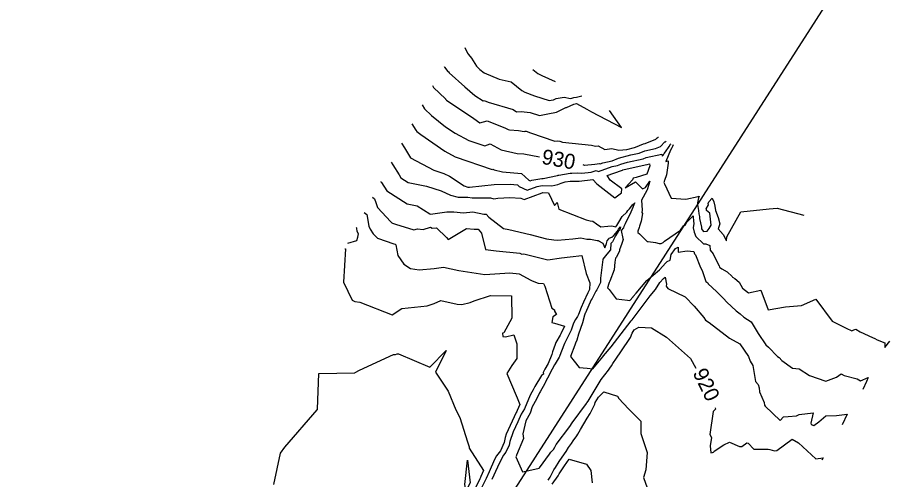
# Model space of a CAD drawing. Extents: x 1368651 to 1378602, y 762048 to 779328.
# Drawn here: x 1376956 to 1377539, y 763159 to 763468 of the extents above; entities that cross this region are included whole.
import ezdxf

# ---------------------------------------------------------------- set-up
doc = ezdxf.new("R2010")
doc.units = 0
for name, color, linetype in [('DTM Contours Major', 7, 'Continuous'), ('DTM Contours Major Text', 7, 'Continuous'), ('DTM Contours Minor', 7, 'Continuous'), ('Exist Plan Preparation Watershed Red', 7, 'Continuous')]:
    doc.layers.add(name, color=color, linetype=linetype)

msp = doc.modelspace()

# ---------------------------------------------------------------- linework, layer by layer
at = {"layer": 'DTM Contours Major'}
for points in [[(1377226.34, 763409.54), (1377228.05, 763406.79), (1377232.64, 763402.32), (1377242.04, 763394.83), (1377248.34, 763390.66), (1377257.44, 763385.77), (1377268.2, 763382.06), (1377271.73, 763383.39), (1377279.11, 763379.49), (1377289.89, 763377.04), (1377294.24, 763376.77), (1377304.68, 763374.81)], [(1377333.65, 763369.59), (1377334.52, 763369.28), (1377334.67, 763369.27), (1377334.74, 763369.27), (1377334.8, 763369.29), (1377341.71, 763369.89), (1377344.73, 763370.29), (1377345.25, 763370.09), (1377347.02, 763370.72), (1377353.34, 763372.05), (1377357.54, 763373.85), (1377365.81, 763376.03), (1377371.39, 763377.26), (1377375.08, 763378.85), (1377382.22, 763380.32), (1377385.45, 763381.63), (1377388.52, 763384.7), (1377388.76, 763384.81), (1377389.39, 763385.24)], [(1377193.17, 763347.84), (1377194.49, 763346.69), (1377195.46, 763344.29), (1377196.55, 763340.94), (1377205.54, 763331.33), (1377205.85, 763330.88), (1377206.12, 763330.62), (1377206.46, 763330.5), (1377208.63, 763329.75), (1377220.75, 763326.09), (1377223.31, 763326.66), (1377227.11, 763326.28), (1377231.97, 763327.88), (1377233.13, 763327.2), (1377236.03, 763327.31), (1377242.53, 763320.93), (1377243.83, 763319.6), (1377255.95, 763326.96), (1377261.15, 763326.53), (1377263.72, 763326.55), (1377266.01, 763323.75), (1377268.72, 763312.89), (1377275.71, 763311.98), (1377291.54, 763310.46), (1377292.92, 763309.72), (1377294.24, 763309.88), (1377310.24, 763306.02), (1377319.4, 763307.37), (1377325.11, 763307.88), (1377332.98, 763308.92), (1377335.89, 763296.77), (1377338.33, 763290.51), (1377338.2, 763286.11), (1377337.45, 763284.91), (1377336.97, 763284), (1377334.08, 763277.7), (1377332.51, 763274.22), (1377330.75, 763269.51), (1377330.18, 763268.24), (1377328.8, 763266.16), (1377327.46, 763263.75), (1377325.96, 763259.1), (1377324.58, 763256.27), (1377321.46, 763250), (1377320.92, 763249.05), (1377318.26, 763241.98), (1377318.09, 763241.49), (1377317.98, 763240.99), (1377315.28, 763236.56), (1377314.79, 763235.76), (1377311.65, 763229.97), (1377311.68, 763229.84), (1377308.56, 763223.96), (1377308.43, 763223.87), (1377308.2, 763223.49), (1377305.12, 763217.85), (1377304.78, 763217.13), (1377302.67, 763212.92), (1377299.92, 763207.87), (1377298.6, 763203.67), (1377295.57, 763198.44), (1377293.54, 763189.87), (1377293.96, 763186.55), (1377289.39, 763175.54), (1377289.33, 763175.39), (1377289.27, 763175.27), (1377288.93, 763174.43), (1377292.5, 763166.51), (1377293.32, 763164.36), (1377295.62, 763164.89), (1377304.45, 763166.79), (1377304.64, 763167.05), (1377304.68, 763167.09), (1377304.71, 763167.15), (1377311.43, 763176.28), (1377312.3, 763177.58), (1377313.99, 763179.21), (1377314.94, 763180.98), (1377315.9, 763182.65), (1377325, 763194.67), (1377326.6, 763197.22), (1377336.14, 763210.13), (1377336.45, 763210.55), (1377337.26, 763211.52), (1377345.96, 763225.99), (1377350.93, 763232.37), (1377351.71, 763233.65), (1377352.79, 763235.23), (1377353.72, 763236.65), (1377356.11, 763240.39), (1377359.12, 763244.55), (1377365.43, 763254.17), (1377366.66, 763256.98), (1377367.97, 763259.2), (1377371.18, 763260.92), (1377379.59, 763260.51), (1377389.57, 763254.28), (1377405.49, 763240.06), (1377409.07, 763233.67)], [(1377422.1, 763207.07), (1377422.31, 763206.34), (1377420.62, 763204.69), (1377418.51, 763189.42), (1377419.71, 763187.29), (1377418.76, 763181.85), (1377419.16, 763177.08), (1377420.35, 763177.41), (1377420.98, 763177.51), (1377421.22, 763177.77), (1377421.45, 763178.1), (1377427.92, 763182.39), (1377431.72, 763184.1), (1377438.38, 763181.27), (1377439.94, 763181.41), (1377443.27, 763183.82), (1377444.18, 763183.46), (1377447.88, 763179.56), (1377457.43, 763179.52), (1377458.55, 763179.33), (1377461.72, 763178.5), (1377463.19, 763178.75), (1377473.46, 763186.11), (1377477.73, 763183.82), (1377489.27, 763173.11), (1377494.08, 763173.75), (1377493.32, 763172.09)]]:
    msp.add_lwpolyline(points, dxfattribs=at)
at = {"layer": 'DTM Contours Minor'}
for points in [[(1377254.92, 763447.86), (1377256.59, 763443.93), (1377257.28, 763443.07), (1377259.31, 763440.73), (1377262.59, 763435.26), (1377265, 763433.13), (1377267.84, 763430.76), (1377277.72, 763426.73), (1377285.84, 763424.93), (1377292.98, 763419.05), (1377294.92, 763418.02), (1377301.3, 763415.44), (1377311.18, 763412.31), (1377312.63, 763412.62), (1377314.15, 763412.89), (1377315.77, 763413.71), (1377321.22, 763414.64), (1377325.44, 763413.61), (1377326.39, 763414.03), (1377327.77, 763414.39), (1377329.51, 763414.7), (1377332.99, 763415.56)], [(1377241.18, 763435.15), (1377241.4, 763434.63), (1377243.63, 763431.85), (1377243.9, 763431.54), (1377244.34, 763430.8), (1377254.9, 763421.46), (1377261.65, 763415.82), (1377267.02, 763412.08), (1377267.84, 763412.31), (1377270.49, 763411.24), (1377287.15, 763406.37), (1377289.44, 763404.78), (1377292.4, 763405.14), (1377298.58, 763404.34), (1377304.73, 763402.4), (1377310.25, 763403.58), (1377316.07, 763404.62), (1377322.26, 763407.75), (1377322.52, 763407.79), (1377322.72, 763407.74), (1377327.68, 763409.96), (1377329.52, 763410.43), (1377336.36, 763406.58), (1377339.49, 763404.78), (1377359.42, 763394.24), (1377351.44, 763405.64)], [(1377300.3, 763433.13), (1377303.56, 763430.44), (1377306.34, 763428.97), (1377315.19, 763425.12)], [(1377233.23, 763422.35), (1377234.01, 763421.1), (1377241.89, 763413.42), (1377242.01, 763413.27), (1377242.63, 763412.71), (1377260.95, 763400.27), (1377264.88, 763397.54), (1377269.84, 763398.89), (1377281.57, 763394.14), (1377283.75, 763392.99), (1377284.7, 763392.78), (1377290.63, 763392.41), (1377294.45, 763391.72), (1377295.14, 763391.86), (1377295.89, 763391.81), (1377298.73, 763390.79), (1377314.96, 763385.26), (1377317.08, 763385.51), (1377318.33, 763385.2), (1377320.19, 763384.53), (1377339.5, 763382.59), (1377342.11, 763381.83), (1377343.98, 763382.08), (1377348.3, 763379.76), (1377353.08, 763380.4), (1377357.77, 763379.28), (1377363.05, 763379.61), (1377368.1, 763380.94), (1377368.9, 763381.12), (1377374.29, 763383.43), (1377375.22, 763383.62), (1377382.37, 763386.52), (1377383.37, 763387.51), (1377384.08, 763387.83), (1377384.3, 763387.98)], [(1377219.45, 763396.72), (1377222.1, 763392.49), (1377222.82, 763391.78), (1377225.44, 763389.69), (1377241.59, 763378.49), (1377248.43, 763374.82), (1377273.14, 763366.31), (1377273.57, 763366.47), (1377274.48, 763366), (1377280.07, 763364.72), (1377292.72, 763363.72), (1377297.69, 763359.11), (1377298.59, 763358.7), (1377299.69, 763359.12), (1377306.22, 763360.33), (1377307.29, 763360.31), (1377316.77, 763362.25), (1377317.17, 763362.41), (1377317.66, 763362.55), (1377325.13, 763363.93), (1377326.39, 763363.91), (1377330.11, 763364.12), (1377332.99, 763363.89), (1377339.29, 763364.62), (1377342.65, 763365.59), (1377344.2, 763365), (1377353.29, 763368.23), (1377356.73, 763368.95), (1377359.01, 763369.93), (1377363.52, 763371.12), (1377373.88, 763373.41), (1377375.87, 763374.27), (1377386.51, 763376.47), (1377386.69, 763375.1), (1377387.5, 763376.17), (1377388.06, 763376.98), (1377388.78, 763378.09), (1377391.29, 763381.58), (1377392.31, 763383.16), (1377392.64, 763383.49)], [(1377212.56, 763383.91), (1377214.59, 763380.66), (1377218.66, 763374.19), (1377234.17, 763365.8), (1377240.77, 763363.72), (1377244.57, 763361.95), (1377254.5, 763355.4), (1377256.89, 763354.6), (1377257.96, 763354.43), (1377274.49, 763356.19), (1377285.15, 763356.4), (1377290.08, 763356.01), (1377291.26, 763354.92), (1377296.56, 763352.45), (1377303.11, 763354.95), (1377306.59, 763355.59), (1377312.94, 763355.48), (1377317.03, 763356.32), (1377319.22, 763357.18), (1377321.95, 763357.97), (1377325.26, 763358.58), (1377329.36, 763358.51), (1377330.46, 763358.57), (1377331.31, 763358.51), (1377340.4, 763359.56), (1377343, 763356.72), (1377354.99, 763347.32), (1377359.41, 763350.72), (1377359.76, 763353.32), (1377351.97, 763359.25), (1377350.03, 763362.35), (1377359.55, 763365.73), (1377360.12, 763365.85), (1377360.49, 763366.01), (1377361.23, 763366.2), (1377376.37, 763369.56), (1377376.66, 763369.69), (1377378.24, 763370.02), (1377378.4, 763368.83), (1377376.37, 763363.1), (1377369.4, 763361.02), (1377367.25, 763360.43), (1377366.79, 763359.4), (1377361.88, 763354.15), (1377368.8, 763358.08), (1377373.51, 763353.3), (1377375.48, 763354.37), (1377378.52, 763358.59), (1377376.65, 763352.79), (1377376.65, 763352.71), (1377376.38, 763352.27), (1377372.92, 763345.71), (1377373.28, 763339.19), (1377373.17, 763337.5), (1377373.46, 763337.02), (1377372.6, 763331.8), (1377371.58, 763328.5), (1377371.32, 763327.65), (1377370.39, 763325.04), (1377370.46, 763324.22), (1377371.59, 763323.39), (1377376.7, 763318.2), (1377377.41, 763318.13), (1377382.25, 763317.61), (1377384.7, 763316.82), (1377385.92, 763316.82), (1377387.26, 763317.46), (1377388.26, 763318.47), (1377398.98, 763325.85), (1377400.93, 763328.66), (1377401.99, 763329.11), (1377402.39, 763329.87), (1377402.88, 763330.82), (1377403.84, 763331.79), (1377406.38, 763334.46), (1377407.3, 763335.25), (1377407.38, 763334.88), (1377407.48, 763331.74), (1377407.82, 763330.28), (1377407.41, 763327.33), (1377407.92, 763324.51), (1377409.18, 763321.49), (1377414.28, 763316.57), (1377415.72, 763316.69), (1377418.41, 763315.54), (1377418.73, 763312.44), (1377420.8, 763309.98), (1377421.27, 763308.81), (1377424.69, 763301.98), (1377424.99, 763301.06), (1377426.52, 763299.99), (1377430.05, 763298.07), (1377433.4, 763294.91), (1377433.6, 763294.49), (1377435.14, 763293.56), (1377438.18, 763290.99), (1377440.34, 763287.11), (1377444.35, 763284.03), (1377452.58, 763285.8), (1377457.41, 763272.57), (1377468.92, 763274.61), (1377479.64, 763275.47), (1377489.27, 763279.73), (1377500.12, 763265.06), (1377509.58, 763260.38), (1377513.32, 763258.61), (1377514.7, 763259.25), (1377516.02, 763259.63), (1377518.93, 763257.87), (1377527.06, 763254.17), (1377528.69, 763253.52), (1377530.19, 763252.61), (1377535.38, 763250.45), (1377535.28, 763247.48), (1377538.79, 763251.57)], [(1377394.05, 763382.74), (1377393.47, 763381.55), (1377393.27, 763381.18), (1377393.08, 763380.81), (1377392.13, 763379.13), (1377389.05, 763371.69), (1377390.63, 763371.98), (1377390.65, 763370.62), (1377389.49, 763362.74), (1377388.32, 763359.05), (1377388.1, 763358.44), (1377387.92, 763358.06), (1377387.84, 763357.51), (1377388.16, 763356.82), (1377392.57, 763347.11), (1377402.36, 763346.59), (1377402.36, 763346.59), (1377410.64, 763348.38), (1377411.28, 763348.47), (1377411.07, 763347.72), (1377410.99, 763347.47), (1377410.15, 763344.12), (1377410.28, 763342.92), (1377410.42, 763341.68), (1377410.98, 763339.02), (1377411.2, 763336.74), (1377411.6, 763334.84), (1377411.64, 763333.66), (1377412.97, 763327.9), (1377412.88, 763327.27), (1377412.99, 763326.66), (1377413.26, 763326.01), (1377414.36, 763324.95), (1377416.72, 763325.15), (1377417.98, 763326.79), (1377419.3, 763329.18), (1377418.42, 763337.17), (1377416.32, 763338.99), (1377416.2, 763339.57), (1377416.06, 763340.08), (1377417.49, 763342.7), (1377417.38, 763343.61), (1377417.74, 763344.77), (1377419.94, 763347.15), (1377421.11, 763344.69), (1377421.8, 763341.74), (1377422.22, 763338.81), (1377423.99, 763334.18), (1377425.15, 763330.03), (1377423.97, 763326.66), (1377427.32, 763322.85), (1377428.25, 763321.27), (1377429.34, 763318.9), (1377429.51, 763318.7), (1377429.61, 763318.89), (1377429.77, 763321.27), (1377439.27, 763337.96), (1377458.14, 763340.06), (1377463.54, 763340.55), (1377481.37, 763335.8)], [(1377205.67, 763371.09), (1377206.73, 763369.39), (1377210.92, 763362.75), (1377212.2, 763360.82), (1377217.06, 763357.7), (1377229.19, 763355.12), (1377239.13, 763351.99), (1377245.26, 763349.12), (1377250.46, 763347.85), (1377256.99, 763347.89), (1377259.78, 763347.48), (1377272.06, 763347.43), (1377274.18, 763346.78), (1377276.91, 763347.25), (1377284.93, 763347.68), (1377292.35, 763347.21), (1377294.54, 763346.2), (1377306.53, 763350.77), (1377306.96, 763350.85), (1377310.75, 763350.79), (1377314.83, 763342.31), (1377316.58, 763344.32), (1377317.76, 763339.78), (1377335.87, 763332.67), (1377338.64, 763332.06), (1377340.32, 763331.89), (1377342.87, 763329.91), (1377345.63, 763328), (1377350.28, 763328.51), (1377352.97, 763328.77), (1377355.64, 763328.02), (1377355.64, 763328.01), (1377355.64, 763328.02), (1377356.36, 763328.94), (1377356.36, 763328.94), (1377357.8, 763331.02), (1377357.81, 763331.03), (1377360.03, 763334.95), (1377360.04, 763334.95), (1377363.16, 763337.88), (1377363.68, 763338.83), (1377364.75, 763340.05), (1377366.42, 763342.06), (1377366.94, 763342.68), (1377368.43, 763344.13), (1377367.79, 763342.62), (1377367.04, 763340.89), (1377365.77, 763337.75), (1377364.85, 763335.81), (1377363.65, 763333.76), (1377361.86, 763330.11), (1377361.17, 763328.31), (1377360.94, 763327.39), (1377359.31, 763325.59), (1377360.31, 763320.14), (1377360.63, 763319.51), (1377360.43, 763318.89), (1377359.77, 763316.91), (1377358.19, 763312.63), (1377358.24, 763311.98), (1377356.07, 763307.73), (1377355.51, 763307.07), (1377355.09, 763304.52), (1377354.53, 763299.26), (1377351.75, 763291.8), (1377351.32, 763290.85), (1377350.99, 763290.23), (1377350.07, 763287.29), (1377351.17, 763286.14), (1377355.92, 763279.85), (1377363.6, 763279.05), (1377365.15, 763278.8), (1377367.32, 763281.32), (1377367.37, 763281.38), (1377369.24, 763283.63), (1377376.46, 763292.14), (1377384.83, 763299.21), (1377389.13, 763304.07), (1377390, 763304.78), (1377392, 763305.74), (1377392.77, 763309.62), (1377395.48, 763313.53), (1377397.42, 763314.36), (1377397.25, 763313.05), (1377397.44, 763311.06), (1377403.3, 763311.93), (1377407.82, 763311.6), (1377408.33, 763309.98), (1377408.95, 763309.26), (1377412.34, 763300.9), (1377413.35, 763298.9), (1377415.71, 763291.53), (1377417.08, 763290.57), (1377417.43, 763289.89), (1377422.93, 763284.77), (1377427.69, 763280.26), (1377429.87, 763277.78), (1377436.03, 763271.93), (1377438.82, 763270), (1377441.19, 763267.7), (1377446.12, 763264.51), (1377450.87, 763256.87), (1377455.91, 763249.29), (1377457.61, 763247.66), (1377463.59, 763241.38), (1377464.77, 763240.76), (1377466.59, 763238.74), (1377473.65, 763233.64), (1377478.26, 763233.27), (1377485.07, 763228.71), (1377495.94, 763225.05), (1377503.12, 763227.66), (1377506.1, 763229.85), (1377508.28, 763228.67), (1377516.96, 763226.57), (1377519.15, 763225.08), (1377524.23, 763227.29), (1377523.06, 763224.77), (1377520.61, 763219.35)], [(1377198.78, 763358.27), (1377198.87, 763358.13), (1377199.24, 763357.55), (1377202.82, 763352.14), (1377216.47, 763343.39), (1377223.06, 763341.99), (1377231.46, 763336.59), (1377231.84, 763336.47), (1377231.92, 763336.42), (1377232, 763336.42), (1377242.87, 763337.96), (1377244.53, 763337.93), (1377247.44, 763338.06), (1377253.99, 763337.31), (1377260.21, 763338.03), (1377267.67, 763336.53), (1377269.2, 763336.54), (1377270.91, 763334.46), (1377280.69, 763326.94), (1377284.26, 763326.12), (1377298.41, 763322.99), (1377309.45, 763319.99), (1377314.3, 763319.25), (1377316.87, 763319.05), (1377327.06, 763319.96), (1377332.43, 763320.67), (1377336.3, 763319.82), (1377338.71, 763319.75), (1377343.28, 763318.91), (1377343.49, 763318.84), (1377343.92, 763318.9), (1377344.22, 763318.82), (1377344.19, 763318.63), (1377347.03, 763317.09), (1377348.43, 763314.01), (1377349.29, 763316.17), (1377349.57, 763316.92), (1377349.57, 763316.97), (1377349.88, 763318.66), (1377351.06, 763319.98), (1377351.26, 763320.53), (1377352.99, 763321.02), (1377353.16, 763321.2), (1377353.49, 763321.53), (1377354.4, 763322.18), (1377356.87, 763325.12), (1377357.36, 763326.24), (1377357.51, 763326.43), (1377358.92, 763327.92), (1377358.46, 763326.11), (1377357.28, 763324.8), (1377355.49, 763322.06), (1377353.45, 763317.94), (1377353.25, 763317.71), (1377353.15, 763317.6), (1377352.91, 763317.24), (1377352.31, 763316.79), (1377352.05, 763312.74), (1377352.07, 763312.46), (1377352.04, 763312.41), (1377348.83, 763308.58), (1377347.02, 763306.45), (1377346.95, 763306.48), (1377346.98, 763306.28), (1377345.46, 763293.68), (1377345.47, 763290.82), (1377342.92, 763285.89), (1377342.38, 763285.02), (1377339.81, 763280.22), (1377339.33, 763279.16), (1377335.45, 763270.59), (1377335.33, 763270.26), (1377334.74, 763269.05), (1377333.42, 763263.88), (1377330.73, 763256.37), (1377329.64, 763252.22), (1377328.83, 763250.3), (1377328.41, 763249.06), (1377325.37, 763241.39), (1377327.8, 763238.32), (1377331.21, 763234.16), (1377336.56, 763233.7), (1377340.39, 763233.23), (1377347, 763241.2), (1377347.55, 763241.84), (1377352.49, 763247.79), (1377366.04, 763265.18), (1377366.72, 763265.96), (1377367.24, 763266.69), (1377367.39, 763266.86), (1377378.55, 763281.89), (1377382.25, 763286.17), (1377385.1, 763290.73), (1377387.56, 763293.5), (1377388.71, 763294.45), (1377389.51, 763289.78), (1377389.28, 763288.28), (1377390.39, 763286.73), (1377401.91, 763281.33), (1377408.11, 763275), (1377414.4, 763267.54), (1377415.54, 763265.77), (1377418.15, 763264.08), (1377431.59, 763253.74), (1377438.53, 763249.78), (1377444.21, 763241.36), (1377445.47, 763238.29), (1377447.26, 763235.31), (1377449.01, 763224.63), (1377450.87, 763222.74), (1377451.49, 763220.4), (1377451.73, 763217.72), (1377454.8, 763210.77), (1377455.01, 763208.99), (1377455.39, 763208.28), (1377465.49, 763198.58), (1377467.74, 763201.11), (1377470.81, 763201.36), (1377476.3, 763201.85), (1377478.06, 763202.7), (1377487.61, 763203.81), (1377485.87, 763196.97), (1377486.11, 763196.11), (1377487.93, 763195.31), (1377491.18, 763197.81), (1377495.94, 763201.76), (1377502.98, 763202.02), (1377510.26, 763202.99), (1377506.97, 763195.72)], [(1377187.69, 763337.65), (1377189.32, 763336.23), (1377190.72, 763328.42), (1377191.72, 763326.45), (1377193.66, 763323.31), (1377196.6, 763320.48), (1377207.36, 763316.74), (1377208.43, 763316.37), (1377208.89, 763315.89), (1377210.16, 763308.8), (1377214.11, 763303.04), (1377218.7, 763300.2), (1377224.39, 763299.36), (1377234.34, 763300.09), (1377240.71, 763301.04), (1377250.91, 763298.79), (1377268.14, 763296.27), (1377284.82, 763297.24), (1377291.19, 763296.63), (1377299.03, 763292.38), (1377299.77, 763291.93), (1377303.9, 763290.39), (1377307.42, 763290.18), (1377308.33, 763288.42), (1377313.01, 763273.79), (1377314.82, 763272.66), (1377314.73, 763271.6), (1377316.05, 763269.55), (1377313.57, 763267.96), (1377312.99, 763264.05), (1377314.83, 763263.76), (1377321.39, 763261.62), (1377318.91, 763256.55), (1377318.44, 763255.61), (1377315.71, 763250.8), (1377315.22, 763249.5), (1377313.45, 763244.61), (1377313.06, 763242.82), (1377310.63, 763236.77), (1377308.29, 763232.94), (1377307.16, 763230.84), (1377307.38, 763229.65), (1377306, 763228.64), (1377301.62, 763221.4), (1377300.41, 763219.19), (1377299.55, 763217.63), (1377298.49, 763215.7), (1377294.62, 763206.42), (1377292.57, 763202.88), (1377290.17, 763197.77), (1377287.1, 763191.16), (1377285, 763184.67), (1377284.51, 763182.2), (1377282.22, 763177.55), (1377280.67, 763175.52), (1377277.57, 763169.56), (1377276.68, 763167.53), (1377272.89, 763159.18)], [(1377176.64, 763317.08), (1377182.69, 763318.8), (1377183.37, 763321.18), (1377183.85, 763323.31), (1377183.07, 763324.85), (1377182.68, 763327.06), (1377182.22, 763327.46)], [(1377174.66, 763313.32), (1377175.29, 763313.33), (1377173.94, 763290.97), (1377179.58, 763279.1), (1377181.43, 763278.08), (1377184.68, 763277.7), (1377206.43, 763269.32), (1377212.83, 763273.54), (1377229.82, 763275.33), (1377234.39, 763276.8), (1377238.76, 763278.79), (1377249.86, 763276.37), (1377252.93, 763276.11), (1377258.42, 763277.48), (1377261.13, 763278.51), (1377272.01, 763282.13), (1377285.98, 763281.92), (1377286.36, 763267.12), (1377281.02, 763257.15), (1377280.03, 763257.04), (1377280.22, 763254.83), (1377282.05, 763254.51), (1377287.67, 763255.82), (1377289.61, 763249.9), (1377289.7, 763240.08), (1377286.37, 763235.44), (1377282.83, 763230.05), (1377289.14, 763215.32), (1377289.25, 763215.03), (1377289.27, 763215.02), (1377291.53, 763209.34), (1377289.86, 763205.33), (1377289.55, 763204.8), (1377289.19, 763204.03), (1377282.47, 763189.59), (1377281.73, 763187.31), (1377281.08, 763184.04), (1377278.59, 763178.39), (1377276.07, 763175.09), (1377274.77, 763172.6), (1377271.16, 763164.37), (1377269.14, 763159.93), (1377265.06, 763151.84)], [(1377127.43, 763155.99), (1377131.75, 763176.95), (1377134.69, 763180.87), (1377156.32, 763205.84), (1377156.4, 763205.95), (1377156.4, 763205.97), (1377156.43, 763206.31), (1377157.31, 763230.07), (1377181.43, 763230.6), (1377181.54, 763230.78), (1377181.54, 763230.78), (1377184.48, 763232.2), (1377207.34, 763242.77), (1377208.55, 763242.72), (1377209.72, 763243.21), (1377210.64, 763243.31), (1377231.43, 763234.32), (1377242.44, 763245.39), (1377235.18, 763230.93), (1377243.84, 763218.27), (1377248.95, 763205.85), (1377251.49, 763200.78), (1377256.67, 763184.39), (1377257.75, 763181.06), (1377257.85, 763180.27), (1377267.42, 763165.28), (1377265.63, 763161.21), (1377265.39, 763160.68), (1377264.91, 763159.72), (1377259.16, 763147.61)], [(1377310.47, 763158.94), (1377311.92, 763160.9), (1377314.37, 763165.77), (1377315.49, 763167.38), (1377317.94, 763171.21), (1377319.97, 763174.13), (1377322.57, 763177.89), (1377324.07, 763180.72), (1377326.22, 763183.26), (1377327.2, 763185.08), (1377329.7, 763188.43), (1377330.36, 763189.6), (1377332.06, 763192.74), (1377336.53, 763200.3), (1377338.49, 763203.27), (1377341.67, 763209.51), (1377342.02, 763210.76), (1377344.17, 763214.37), (1377347.65, 763217.87), (1377356.72, 763214.85), (1377357.72, 763213.33), (1377364.27, 763206.48), (1377372.45, 763198.24), (1377372.45, 763190.06), (1377376.57, 763177.38), (1377375.75, 763165.66), (1377374.11, 763160.57), (1377376.61, 763153.76)], [(1377313.11, 763156.24), (1377317.23, 763161.83), (1377317.9, 763163.17), (1377321.06, 763167.69), (1377321.51, 763168.38), (1377324.56, 763172.79), (1377336.16, 763169.55), (1377339, 763165.35), (1377340.02, 763157.09)], [(1377254.85, 763155.92), (1377256.61, 763172.28), (1377258.49, 763157.09), (1377256.95, 763154.16), (1377255.64, 763152.13), (1377254.85, 763155.92)]]:
    msp.add_lwpolyline(points, dxfattribs=at)
at = {"layer": 'Exist Plan Preparation Watershed Red'}
msp.add_lwpolyline([(1373597.06, 767081.43), (1372938.47, 765818.8), (1372653.04, 765271.58), (1372900.45, 763223.22), (1372954.35, 762776.96), (1374508.77, 762195.85), (1375573.49, 762047.77), (1376441.31, 762392.26), (1376924.99, 762584.25), (1377201.49, 763017.52), (1377601.94, 763641.51), (1377736.1, 764021.28), (1377789.42, 764495.73), (1377827.52, 764834.78), (1378601.52, 765333.49), (1378471.1, 765535.9), (1378572.78, 766627.53)], dxfattribs=at)

# ---------------------------------------------------------------- texts
at = {"layer": 'DTM Contours Major Text'}
for s, rotation, p in [('930', 349.78537, (1377305.68, 763370.18)), ('920', 296.09953, (1377406.82, 763230.52))]:
    msp.add_text(s, height=10, rotation=rotation, dxfattribs=at).set_placement(p)

doc.saveas('drawing.dxf')
